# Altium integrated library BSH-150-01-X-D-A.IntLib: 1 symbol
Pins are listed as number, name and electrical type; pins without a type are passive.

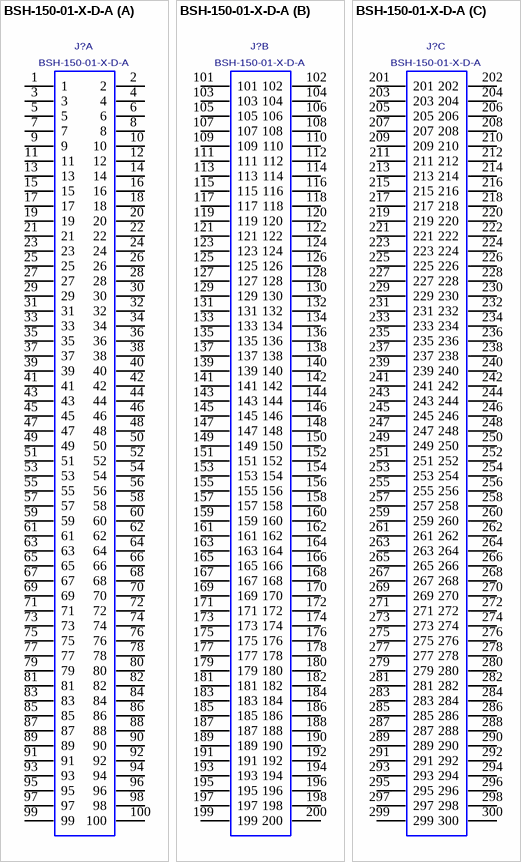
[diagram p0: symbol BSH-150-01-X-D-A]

## BSH-150-01-X-D-A
designator J?
Socket, Dual Row, Surface Mount, 0.5mm Pitch, 300 Pins.; MANUFACTURER: SAMTEC
footprint BSH-150-01-X-D-A
part A pins: 1, 2, 3, 4, 5, 6, 7, 8, 9, 10, 11, 12, 13, 14, 15, 16, 17, 18, 19, 20, 21, 22, 23, 24, 25, 26, 27, 28, 29, 30, 31, 32, 33, 34, 35, 36, 37, 38, 39, 40, 41, 42, 43, 44, 45, 46, 47, 48, 49, 50, 51, 52, 53, 54, 55, 56, 57, 58, 59, 60, 61, 62, 63, 64, 65, 66, 67, 68, 69, 70, 71, 72, 73, 74, 75, 76, 77, 78, 79, 80, 81, 82, 83, 84, 85, 86, 87, 88, 89, 90, 91, 92, 93, 94, 95, 96, 97, 98, 99, 100
part B pins: 101, 102, 103, 104, 105, 106, 107, 108, 109, 110, 111, 112, 113, 114, 115, 116, 117, 118, 119, 120, 121, 122, 123, 124, 125, 126, 127, 128, 129, 130, 131, 132, 133, 134, 135, 136, 137, 138, 139, 140, 141, 142, 143, 144, 145, 146, 147, 148, 149, 150, 151, 152, 153, 154, 155, 156, 157, 158, 159, 160, 161, 162, 163, 164, 165, 166, 167, 168, 169, 170, 171, 172, 173, 174, 175, 176, 177, 178, 179, 180, 181, 182, 183, 184, 185, 186, 187, 188, 189, 190, 191, 192, 193, 194, 195, 196, 197, 198, 199, 200
part C pins: 201, 202, 203, 204, 205, 206, 207, 208, 209, 210, 211, 212, 213, 214, 215, 216, 217, 218, 219, 220, 221, 222, 223, 224, 225, 226, 227, 228, 229, 230, 231, 232, 233, 234, 235, 236, 237, 238, 239, 240, 241, 242, 243, 244, 245, 246, 247, 248, 249, 250, 251, 252, 253, 254, 255, 256, 257, 258, 259, 260, 261, 262, 263, 264, 265, 266, 267, 268, 269, 270, 271, 272, 273, 274, 275, 276, 277, 278, 279, 280, 281, 282, 283, 284, 285, 286, 287, 288, 289, 290, 291, 292, 293, 294, 295, 296, 297, 298, 299, 300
